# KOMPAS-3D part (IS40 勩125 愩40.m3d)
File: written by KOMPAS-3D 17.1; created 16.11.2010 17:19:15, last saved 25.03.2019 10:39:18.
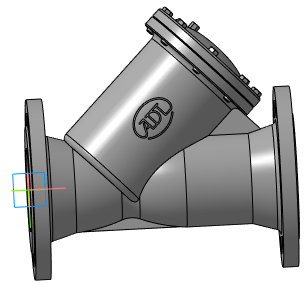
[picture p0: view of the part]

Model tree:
1. Плоскость XY
2. Плоскость ZX
3. Плоскость ZY
4. Ось X
5. Ось Y
6. Ось Z
7. Начало координат
8. Операция без истории:2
